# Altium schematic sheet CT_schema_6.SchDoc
size 221 x 173 mm
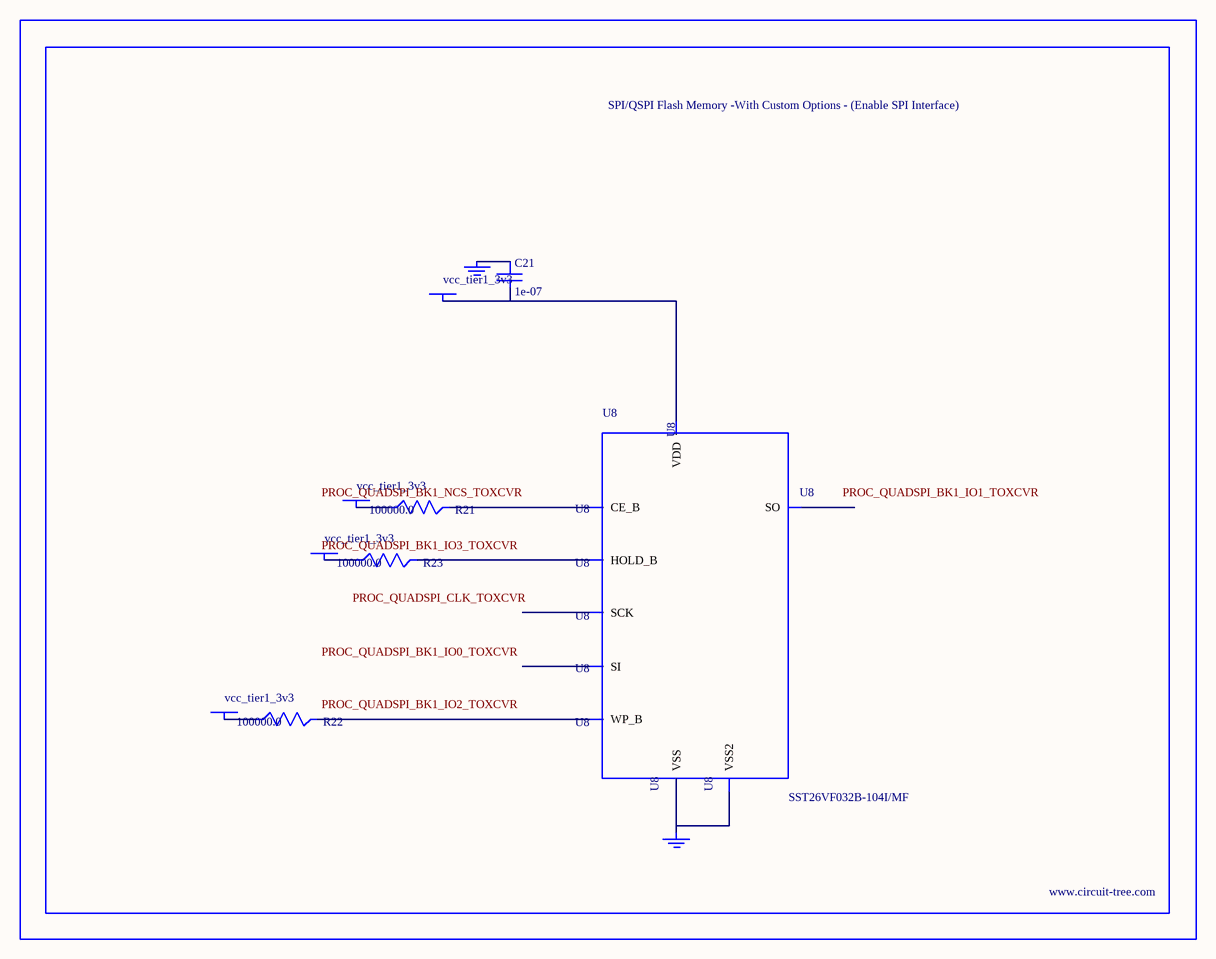
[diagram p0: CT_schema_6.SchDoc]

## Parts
BORDER5  (no value)
C21  1e-07  [C0402]
GND_INSTANCE_5_0  (no value)
GND_INSTANCE_5_1  (no value)
POWER_INSTANCE_5_0  vcc_tier1_3v3
POWER_INSTANCE_5_1  vcc_tier1_3v3
POWER_INSTANCE_5_2  vcc_tier1_3v3
POWER_INSTANCE_5_3  vcc_tier1_3v3
R21  100000.0  [R0603]
R22  100000.0  [R0603]
R23  100000.0  [R0603]
U8  SST26VF032B-104I/MF  [WFDN-8]

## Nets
NetC21_1: C21.1 GND_INSTANCE_5_0.0(GND)
NetC21_2: C21.2 POWER_INSTANCE_5_3.0(PWR) U8.8(VDD)
NetGND_INSTANCE_5_1_0: GND_INSTANCE_5_1.0(GND) U8.4(VSS) U8.9(VSS2)
NetPOWER_INSTANCE_5_0_0: POWER_INSTANCE_5_0.0(PWR) R21.1
NetPOWER_INSTANCE_5_1_0: POWER_INSTANCE_5_1.0(PWR) R22.1
NetPOWER_INSTANCE_5_2_0: POWER_INSTANCE_5_2.0(PWR) R23.1
NetR21_2: R21.2 U8.1(CE_B)
NetR22_2: R22.2 U8.3(WP_B)
NetR23_2: R23.2 U8.7(HOLD_B)

Not connected (* = marked no-connect by the designer): U8 2(SO) 5(SI) 6(SCK)

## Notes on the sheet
- Labels drawn without touching a wire or pin: PROC_QUADSPI_BK1_IO0_TOXCVR, PROC_QUADSPI_BK1_IO1_TOXCVR, PROC_QUADSPI_BK1_IO2_TOXCVR, PROC_QUADSPI_BK1_IO3_TOXCVR, PROC_QUADSPI_BK1_NCS_TOXCVR, PROC_QUADSPI_CLK_TOXCVR

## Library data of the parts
BORDER5 = BORDER_PAGE5
C21 = C0402C104K3RACTU
GND_INSTANCE_5_0 GND_INSTANCE_5_1 = GND
POWER_INSTANCE_5_0-POWER_INSTANCE_5_3 = PWR
R21-R23 = RC0603JR-07100KL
